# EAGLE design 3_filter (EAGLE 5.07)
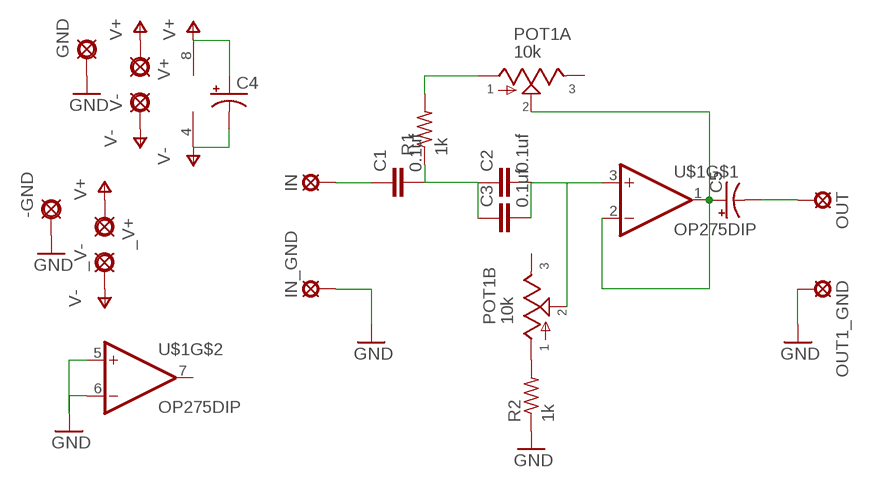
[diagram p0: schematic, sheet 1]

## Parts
-GND  PADOFF  [OFFSET]
_V+  PADOFF  [OFFSET]
_V-  PADOFF  [OFFSET]
C1  0.1uf  050X030_0502  [050X030_050]
C2  0.1uf  050X030_0502  [050X030_050]
C3  0.1uf  050X030_0502  [050X030_050]
C4  0501  [050_020_1]
C5  0501  [050_020_1]
GND  PADOFF  [OFFSET]
IN  MCS10B  [MCS10B]
IN_GND  MCS10B  [MCS10B]
OUT  MCS10B  [MCS10B]
OUT1_GND  MCS10B  [MCS10B]
POT1  10k  DGPOT  [16MM-DUALGANGED]
R1  1k  6MM.3  [R0207/3]
R2  1k  6MM.3  [R0207/3]
U$1  OP275DIP  [DIL08]
V+  PADOFF  [OFFSET]
V-  PADOFF  [OFFSET]

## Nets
GND: -GND.1(PAD) GND.1(PAD) IN_GND.MP OUT1_GND.MP R2.1 U$1.5(+IN) U$1.6(-IN)
N$1: POT1.B1 R2.2
N$2: C1.1 IN.MP
N$3: C1.2 C2.1 C3.1 R1.1
N$4: C5.+ POT1.A2 U$1.1(OUT) U$1.2(-IN)
N$5: C2.2 C3.2 POT1.B2 U$1.3(+IN)
N$6: POT1.A1 R1.2
N$7: C5.- OUT.MP
V+: _V+.1(PAD) C4.+ U$1.8(V+) V+.1(PAD)
V-: _V-.1(PAD) C4.- U$1.4(V-) V-.1(PAD)
Unconnected: POT1.A3 POT1.B3 U$1.7(OUT)

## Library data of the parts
-GND _V+ _V- GND V+ V- = gm-supply:PAD: PAD
C1-C3 = gm-caps-ceramic:050X030_050: 120 - 150pF
C4 C5 = gm-caps-electro-pol:050: 0.22 - 100uF
IN IN_GND OUT OUT1_GND = solpad:MCS10B: SOLDER PAD
POT1 = openmusiclabs_laptop:DGPOT: Dual Ganged Potentiometer two voltage dividers controlled by a single knob the arrow indicates the clockwise motion of th wiper (lug 2) fully counter clockwise there is no resistance between lugs 1 and 2 fully clockwise the resistance between lugs 1 and 2 is the value of the pot Source: taken from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
R1 R2 = gm-resistors:6MM: 6mm Resistors
U$1 = openmusiclabs_laptop:OP275: Dual Bipolar/JFET, Audio Operational Amplifier Analog Devices www.openmusiclabs.com 2010

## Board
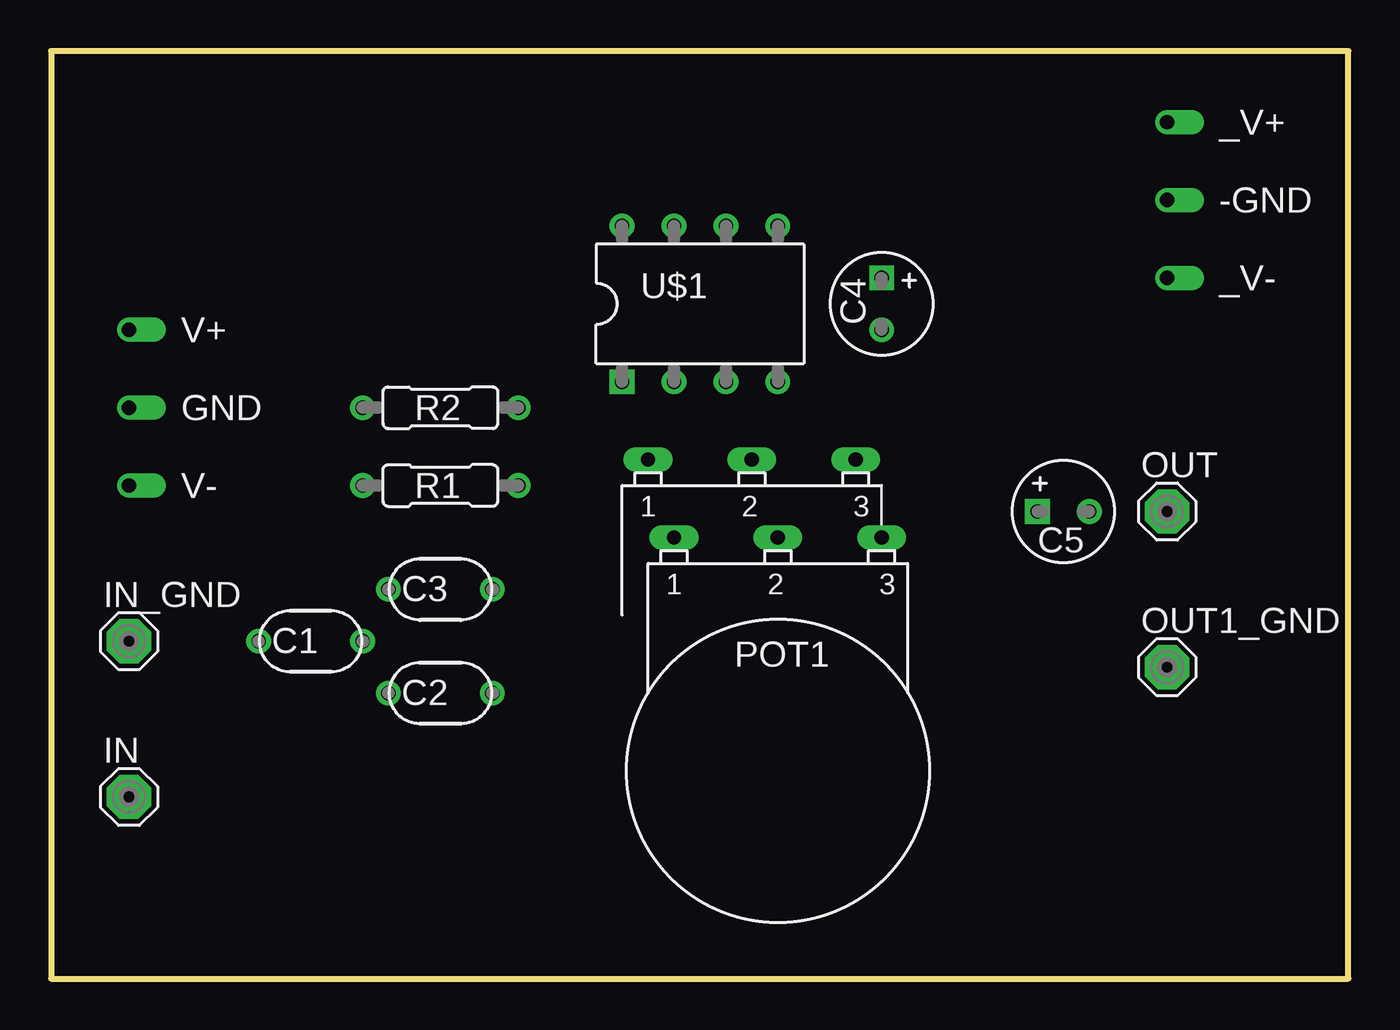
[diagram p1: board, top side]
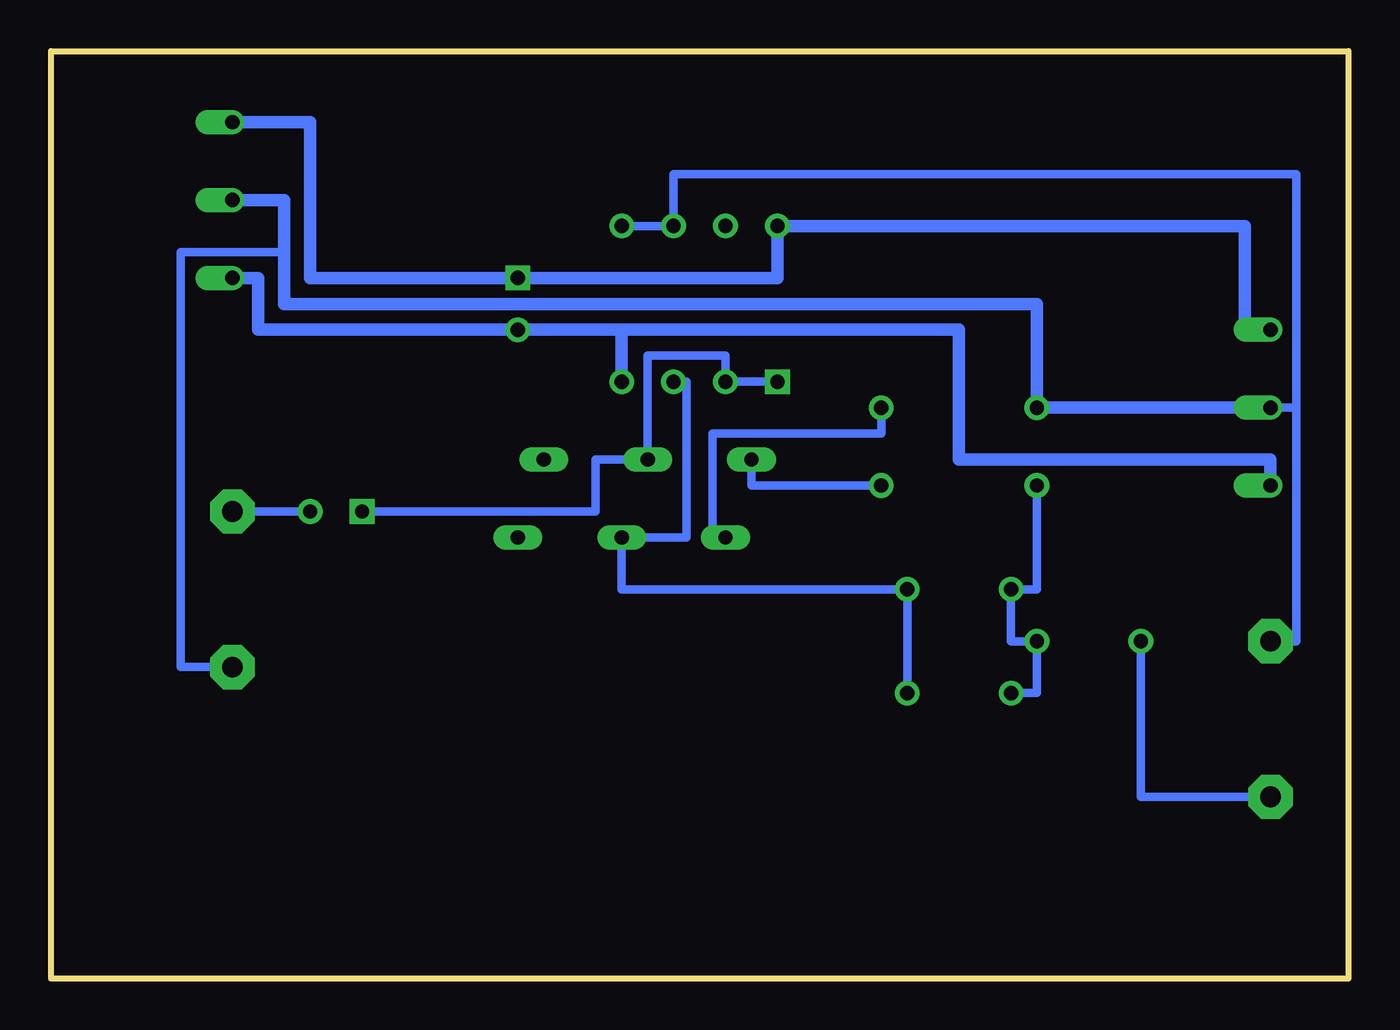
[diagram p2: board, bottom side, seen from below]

Size 63.48 x 45.39 mm. Coordinates in mm from the lower left corner, seen from the top.
Outline: 0,0 63.48,0 63.48,45.39 0,45.39 0,0
Copper layers (1*16): Top 0.035mm / dielectric 1.5mm / Bottom 0.035mm
Design rules "default": minimum track width 10mil, minimum drill 24mil, track to track 8mil, track to pad 8mil, pad to pad 8mil, via to via 8mil, smd to smd 8mil, copper to edge 40mil, drill to drill 8mil, minimum pad ring 10mil, minimum via ring 8mil, stop-mask expansion 4mil, vias tented up to drill 0mil, thermal gap 10mil

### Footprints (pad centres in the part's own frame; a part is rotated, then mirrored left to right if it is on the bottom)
OFFSET = drill 0.7 offset: 1 0,0
050X030_050 = drill 0.7 round: 1 -2.54,0; 2 2.54,0
050_020_1 = drill 0.7 square: + -1.27,0 | drill 0.7 round: - 1.27,0
MCS10B = drill 1.016 pad 2.159 octagon: MP 0,0
16MM-DUALGANGED = drill 0.7 long: A1 6.35,-11.43; A2 1.27,-11.43; A3 -3.81,-11.43; B1 5.08,-7.62; B2 0,-7.62; B3 -5.08,-7.62
R0207/3 = drill 0.7 round: 1 -3.81,0; 2 3.81,0
DIL08 = drill 0.7 square: 1 -3.81,-3.81 | drill 0.7 round: 2 -1.27,-3.81; 3 1.27,-3.81; 4 3.81,-3.81; 5 3.81,3.81; 6 1.27,3.81; 7 -1.27,3.81; 8 -3.81,3.81

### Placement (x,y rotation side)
-GND  54.61,38.1 0 top
_V+  54.61,41.91 0 top
_V-  54.61,34.29 0 top
C1  12.7,16.51 0 top
C2  19.05,13.97 0 top
C3  19.05,19.05 0 top
C4  40.64,33.02 270 top
C5  49.53,22.86 0 top
GND  3.81,27.94 0 top
IN  3.81,8.89 0 top
IN_GND  3.81,16.51 0 top
OUT  54.61,22.86 0 top
OUT1_GND  54.61,15.24 0 top
POT1  35.56,13.97 180 top
R1  19.05,24.13 0 top
R2  19.05,27.94 0 top
U$1  31.75,33.02 0 top
V+  3.81,31.75 0 top
V-  3.81,24.13 0 top

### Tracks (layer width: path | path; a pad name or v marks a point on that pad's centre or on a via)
GND
  Bottom 0.406: 2.54,27.94 2.54,39.37 33.02,39.37 U$1.6 U$1.5 | 2.54,27.94 GND.1 | 2.54,27.94 2.54,16.51 IN_GND.MP | OUT1_GND.MP 57.15,15.24 57.15,35.56 52.07,35.56
  Bottom 0.61: GND.1 R2.1 15.24,33.02 52.07,33.02 52.07,35.56 52.07,38.1 -GND.1
N$1
  Bottom 0.406: R2.2 22.86,26.67 31.12,26.67 31.12,21.59 POT1.B1
N$2
  Bottom 0.406: IN.MP 10.16,8.89 C1.1
N$3
  Bottom 0.406: R1.1 15.24,19.05 C3.1 16.51,16.51 C1.2 15.24,13.97 C2.1
N$4
  Bottom 0.406: C5.+ 36.83,22.86 36.83,25.4 POT1.A2 34.29,30.48 30.48,30.48 U$1.2 U$1.1
N$5
  Bottom 0.406: C2.2 C3.2 35.56,19.05 POT1.B2 32.38,21.59 32.38,29.21 U$1.3
N$6
  Bottom 0.406: R1.2 29.21,24.13 POT1.A1
N$7
  Bottom 0.406: C5.- OUT.MP
V+
  Bottom 0.61: V+.1 5.08,31.75 5.08,36.83 U$1.8 27.94,34.29 C4.+ 50.8,34.29 50.8,41.91 _V+.1
V-
  Bottom 0.61: 35.56,31.75 19.05,31.75 19.05,25.4 3.81,25.4 V-.1 | 35.56,31.75 U$1.4 | 35.56,31.75 C4.- 53.34,31.75 53.34,34.29 _V-.1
